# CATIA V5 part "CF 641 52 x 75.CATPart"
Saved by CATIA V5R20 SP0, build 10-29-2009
Part number: CF 641 52 x 75
Definition: NONE
Nomenclature: CF 641 52 x 75
Source: Unknown
Description: CF 641 52 x 75
Bounding box of the stored display mesh (mm): x -40 to 35, y -39.5 to 39.5, z -39.5 to 39.5
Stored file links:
  C:\Users\Utente\Desktop\IO LAVORO\3D X SITO CF\X SITO\CF 641\CF 641 52 x 75.CATPart
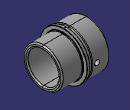
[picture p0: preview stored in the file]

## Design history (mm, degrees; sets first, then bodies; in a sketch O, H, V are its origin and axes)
Body1 "CF 641 52 x 75" (main body)
  Solid1: solid without history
